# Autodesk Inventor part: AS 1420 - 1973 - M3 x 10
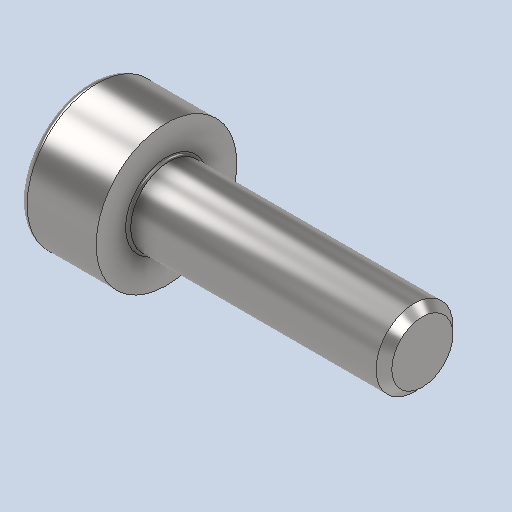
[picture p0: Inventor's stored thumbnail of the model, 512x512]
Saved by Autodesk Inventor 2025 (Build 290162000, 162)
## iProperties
Created: 2024-01
Part Number: AS 1420 - 1973 - M3 x 10
Material: Acciaio, Dolce
Description: Viti con esagono incassato metriche ISO
Document SubType Name: Modeling
Designer: Ryzen5700u
Density: 7.85 g/cm^3
Appearance: Default
Author: Ryzen5700u
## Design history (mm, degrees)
feature "Solid1"
node "Solido1"
